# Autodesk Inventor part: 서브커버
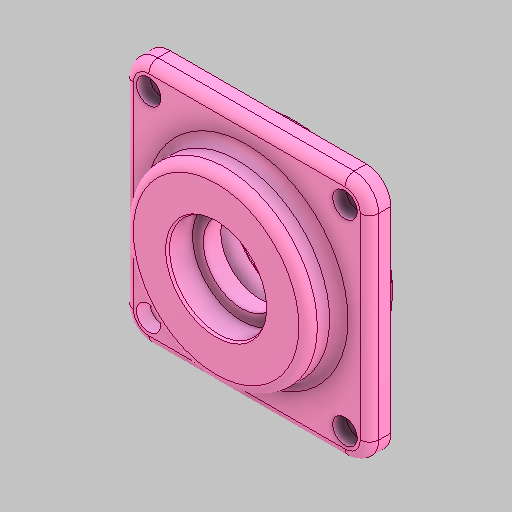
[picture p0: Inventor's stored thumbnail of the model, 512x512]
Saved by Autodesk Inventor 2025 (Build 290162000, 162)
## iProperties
Created: 2024-08
Part Number: 서브커버
Material: 일반
Document SubType Name: Modeling
Designer: 현기
Density: 1 g/cm^3
Appearance: 기본값
Author: jhkim
Sending System: Autodesk Inventor 2025
Preprocessor: ST-DEVELOPER v20
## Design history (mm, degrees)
feature "솔리드1"
node "솔리드2"
